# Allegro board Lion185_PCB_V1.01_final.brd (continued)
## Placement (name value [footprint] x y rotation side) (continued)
R170  2k  [RC0402N]  64.46 122.28 270 top
R171  2k  [RC0402N]  64.47 124.04 90 top
R176  0  [RC0402N]  13.18 36.71 270 top
R178  1M  [RC0402N]  7.56 38.57 0 bottom
R182  1M  [RC0402N]  14.13 34.48 270 top
R184  4.7K  [RC0402N]  52.99 116.09 180 bottom
R185  4.7K  [RC0402N]  65.76 114.96 0 top
R186  4.7K  [RC0402N]  57.01 111.9 270 bottom
R187  4.7K  [RC0402N]  63.72 119.33 270 top
R188  4.7K  [RC0402N]  63.72 117.56 90 top
R189  4.7K  [RC0402N]  57.78 111.9 90 bottom
R190  0  [RC0402N]  94.16 44.17 270 bottom
R191  0  [RC0402N]  94.92 44.17 270 bottom
R192  620  [RC0402N]  144.66 99.61 180 bottom
R193  620  [RC0402N]  144.66 100.42 180 bottom
R194  620  [RC0402N]  144.66 101.2 180 bottom
R195  620  [RC0402N]  144.66 101.98 180 bottom
R196  620  [RC0402N]  144.66 102.76 180 bottom
R197  620  [RC0402N]  144.66 103.54 180 bottom
R198  620  [RC0402N]  144.66 104.31 180 bottom
R199  100k  [RC0402N]  145.92 95.24 90 bottom
R200  620  [RC0402N]  144.66 105.08 180 bottom
R201  1k  [RC0402N]  142.33 110.92 180 bottom
R202  2.2K  [RC0402N]  151.44 101.07 90 bottom
R203  2.2K  [RC0402N]  151.44 98.69 270 bottom
R204  2.2K  [RC0402N]  146.83 102.02 90 bottom
R205  2.2K  [RC0402N]  146.83 99.64 270 bottom
R206  0  [RC0603N]  68.98 46.84 0 bottom
R207  0  [RC0603N]  68.24 48.83 270 bottom
R208  0  [RC0402N]  70.72 43.51 90 bottom
R209  2.49K+/-1  [RC0603N]  60.79 45.45 270 bottom
R210  10k  [RC0402N]  53.67 40.9 0 bottom
R211  0  [RC0603N]  48.12 42.93 90 bottom
R212  1k  [RC0402N]  70.72 45.29 90 bottom
R213  10k  [RC0402N]  51.47 40.86 0 bottom
R214  0  [RC0603N]  46.76 42.93 270 bottom
R215  0  [RC0603N]  47.39 40.94 180 bottom
R216  0  [RC0402N]  51.58 38.89 180 bottom
R217  1k  [RC0402N]  51.6 36.5 180 bottom
R218  0  [RC0402N]  51.59 35.69 180 bottom
R219  15K  [RC0402N]  51.6 37.26 180 bottom
R220  0  [RC0603N]  53.59 34.7 180 bottom
R223  10k  [RC0402N]  59.69 35.99 270 bottom
R226  1K  [RC0402N]  54.5 45.59 270 bottom
R235  0  [RC0402N]  137.74 27.16 270 bottom
R236  0  [RC0402N]  118.49 9.2 0 bottom
R237  10k  [RC0402N]  120.99 9.21 180 bottom
R238  75  [RC0402N]  135.41 17.81 180 bottom
R239  10k  [RC0402N]  120.99 9.99 180 bottom
R240  0  [RC0402N]  109.94 17 180 bottom
R241  75  [RC0402N]  135.24 18.59 180 bottom
R242  1K  [RC0603N]  132.44 26.99 90 bottom
R243  0  [RC0402N]  111.32 12.33 0 bottom
R244  4.7K  [RC0402N]  135.86 21.62 270 top
R245  1K  [RC0603N]  131.16 26.99 90 bottom
R246  4.7K  [RC0402N]  135.03 21.62 270 top
R247  0  [RC0402N]  26.28 45.51 270 bottom
R248  0  [RC0402N]  86 36.04 180 bottom
R249  4.7K  [RC0402N]  130.13 32.77 90 bottom
R251  39.2K  [RC0402N]  126.07 23.8 270 bottom
R252  20K  [RC0402N]  127.64 23.8 90 bottom
R256  20K  [RC0402N]  126.85 23.8 270 bottom
R258  0  [RC0603N]  123.06 20.05 180 bottom
R260  0  [RC0603N]  123.06 21.27 180 bottom
R262  33  [RC0402N]  124.37 19.06 180 bottom
R267  10k  [RC0402N]  133.3 23.78 0 top
R268  10k  [RC0402N]  133.3 23 0 top
R269  10k  [RC0402N]  115.38 16.82 0 bottom
R270  10k  [RC0402N]  119.59 19.02 270 bottom
R271  100k  [RC0402N]  119.59 20.81 90 bottom
R272  0  [RC0402N]  115.48 19 270 bottom
R275  1K  [RC0402N]  120.04 24.12 0 bottom
R278  0  [RC0402N]  48.98 33.01 90 bottom
R279  0  [RC0402N]  42.98 42.33 180 bottom
R280  0  [RC0402N]  43.18 46.34 0 bottom
R281  0  [RC0402N]  43.18 47.14 0 bottom
R282  0  [RC0402N]  51.31 54.72 0 bottom
R283  0  [RC0603N]  126.76 10.96 90 bottom
R284  0  [RC0603N]  125.55 10.96 90 bottom
R285  0  [RC0603N]  129.22 11.74 90 bottom
R286  0  [RC0603N]  127.98 11.09 90 bottom
R290  0  [RC0402N]  106.07 40.16 180 bottom
R291  0  [RC0402N]  106.07 40.93 180 bottom
R292  0  [RC0402N]  101.79 44.17 90 bottom
R293  0  [RC0402N]  90.38 104.88 135 bottom
R296  10k  [RC0402N]  96.78 46.16 270 bottom
R297  10k  [RC0402N]  97.85 46.15 270 bottom
R298  10k  [RC0402N]  108.54 22.69 90 bottom
R299  10k  [RC0402N]  93.36 44.17 270 bottom
R300  10k  [RC0402N]  95.72 44.17 270 bottom
R301  0  [RC0402N]  86 35.03 180 bottom
R302  10k  [RC0402N]  98.71 44.15 270 bottom
R304  0  [RC0603N]  109.12 36.53 0 bottom
R307  0  [RC0402N]  87 39.49 90 bottom
R308  0  [RC0402N]  23.84 36.15 180 top
R310  10k  [RC0402N]  86 36.84 0 bottom
R311  5.6k  [RC0402N]  107.38 30.39 270 bottom
R312  100  [RC0402N]  106.12 30.11 0 bottom
R313  10k  [RC0402N]  111.46 30.76 90 bottom
R314  100k  [RC0402N]  110.22 28.73 270 bottom
R315  10k  [RC0402N]  99.84 44.15 270 bottom
R316  10k  [RC0402N]  86 37.62 0 bottom
R317  0  [RC0402N]  108.76 45.64 90 bottom
R318  0  [RC0402N]  109.12 34.28 180 bottom
R319  0  [RC0402N]  107.08 27.22 90 bottom
R320  10k  [RC0402N]  105.51 27.65 270 bottom
R321  0  [RC0402N]  109.05 39.51 180 bottom
R322  0  [RC0402N]  89.83 44.09 90 bottom
R323  0  [RC0402N]  96.68 24.46 90 bottom
R324  0  [RC0402N]  106.09 33.78 180 bottom
R325  0  [RC0402N]  95.91 24.46 270 bottom
R326  20K  [RC0402N]  109.45 28.73 270 bottom
R327  100k  [RC0402N]  113.85 47.08 180 bottom
R328  0  [RC0402N]  106.11 31.66 0 bottom
R329  0  [RC0402N]  102.71 44.17 270 bottom
R330  10k  [RC0402N]  95.1 24.46 90 bottom
R331  0  [RC0402N]  90.89 44.17 90 bottom
R332  0  [RC0402N]  110.01 25.75 135 bottom
R333  100k  [RC0402N]  106.07 35.5 0 bottom
R334  0  [RC0402N]  76.92 42.02 0 bottom
R335  4.7K  [RC0402N]  106.12 30.87 180 bottom
R336  0  [RC0402N]  11.66 27.23 90 bottom
R337  0  [RC0402N]  86.57 27.41 0 bottom
R338  10k  [RC0402N]  86.18 29.13 0 bottom
R339  0  [RC0402N]  76.45 41.54 270 bottom
R340  10k  [RC0402N]  86.47 32.3 0 bottom
R341  0  [RC0402N]  9.56 23.34 180 top
R342  0  [RC0402N]  8.72 31.63 270 top
R343  0  [RC0402N]  104.49 44.11 270 bottom
R344  10M  [RC0402N]  105.26 43.16 90 bottom
R345  4.7K  [RC0402N]  86.99 45.19 0 bottom
R346  4.7K  [RC0402N]  75.38 45.44 270 bottom
R347  100k  [RC0402N]  73.73 40.63 0 bottom
R348  2K  [RC1206N]  102.89 11.57 90 top
R349  0  [RC0402N]  11.2 30.98 0 top
R350  0  [RC0402N]  12.43 27.23 90 bottom
R351  1M  [RC0402N]  15.06 26.9 0 bottom
R352  1k  [RC0402N]  17.98 39.2 0 top
R353  0  [RC0402N]  20.31 39.92 90 top
R354  27K  [RC0402N]  17.79 26.91 0 bottom
R355  0  [RC0402N]  8.85 26.6 90 bottom
R356  10k  [RC0402N]  15.71 36.25 0 top
R357  0  [RC0603N]  115.93 102.02 270 top
R358  0  [RC0402N]  119.04 104.57 270 top
R359  0  [RC0402N]  11.21 31.83 180 top
R360  0  [RC0603N]  133.93 77.28 0 bottom
R361  0  [RC0603N]  133.93 76.03 0 bottom
R362  0  [RC0603N]  133.86 73.41 0 bottom
R363  1.8k  [RC0603N]  130.56 79.88 0 top
R364  0  [RC0603N]  133.86 74.66 0 bottom
R365  1k  [RC0603N]  130.56 78.67 180 top
R366  1k  [RC0402N]  131.06 72.65 180 top
R367  0  [RC0603N]  133.75 78.59 0 bottom
R368  0  [RC0603N]  133.75 79.84 0 bottom
R369  1.8k  [RC0603N]  144.51 56.37 180 bottom
R370  1k  [RC0603N]  144.51 57.65 0 bottom
R371  1k  [RC0402N]  144.86 50.36 0 bottom
R372  1.8k  [RC0603N]  52.34 16.84 180 bottom
R373  1.8k  [RC0603N]  44.21 23.94 270 top
R374  1k  [RC0603N]  52.37 15.61 0 bottom
R375  1k  [RC0402N]  49.85 17.08 0 bottom
R376  100k  [RC0402N]  28.61 47.68 0 bottom
R377  10k  [RC0402N]  132.95 57.9 270 bottom
R378  10k  [RC0402N]  27.7 45.03 0 bottom
R379  1k  [RC0603N]  45.44 23.94 90 top
R380  1k  [RC0402N]  42.79 25.8 0 top
R381  0  [RC0603N]  135.01 48.11 90 top
R382  0  [RC0603N]  30.45 25.2 270 top
R383  0  [RC0402N]  42.27 105.29 90 top
R384  10k  [RC0402N]  55.12 64.62 180 bottom
R385  0  [RC0402N]  20.88 62.34 270 top
R386  10k  [RC0402N]  8.19 103.47 90 bottom
R387  100k  [RC0402N]  17.99 99.9 270 bottom
R388  0  [RC0402N]  17.16 104.74 180 bottom
R389  0  [RC0402N]  13.58 42.77 180 top
R390  100k  [RC0402N]  24.51 91.29 180 bottom
R391  0  [RC0603N]  3.55 13.12 180 bottom
R392  0  [RC0603N]  6.33 13.12 0 bottom
R408  75  [RC0402N]  76.92 24.46 0 bottom
R409  75  [RC0402N]  74.82 24.46 180 bottom
R421  20K  [RC0603N]  29.49 89.77 0 bottom
R422  20K  [RC0603N]  29.41 85.17 0 bottom
R423  30k  [RC0603N]  29.49 91 180 bottom
R424  13k  [RC0603N]  29.4 83.94 0 bottom
R425  270k  [RC0402N]  27.25 89.85 180 bottom
R426  270k  [RC0402N]  28.93 82.92 0 bottom
R427  10k  [RC0402N]  29.01 86.22 180 bottom
R428  10k  [RC0402N]  29.01 87.03 180 bottom
R429  2.2  [RC0603N]  21.88 95.67 270 bottom
R430  2.2  [RC0603N]  26.05 83.78 0 top
R431  0  [RC0603N]  22.61 81.53 270 bottom
R432  0  [RC0603N]  21.62 92.09 270 bottom
R433  0  [RC0402N]  55.12 70.73 180 bottom
R434  0  [RC0402N]  56.39 71.2 90 bottom
R435  0  [RC0402N]  55.59 71.2 90 bottom
R436  200K  [RC0402N]  55.12 62.94 0 bottom
R437  10k  [RC0402N]  11.39 14.11 0 top
R438  110K  [RC0402N]  55.12 63.7 180 bottom
R439  0  [RC0402N]  60.47 64.88 90 bottom
R440  0  [RC0402N]  55.12 65.4 180 bottom
R441  0  [RC0603N]  39.7 79.61 180 bottom
R442  0  [RC0603N]  54.09 67.57 270 bottom
R443  0  [RC0603N]  41.17 73.9 180 bottom
R444  0  [RC0402N]  49.79 60.39 270 bottom
R445  10k  [RC0402N]  48.78 62.47 270 bottom
R446  75K  [RC0402N]  48.01 64.24 270 bottom
R447  30k  [RC0402N]  47.23 64.24 270 bottom
R448  100k  [RC0402N]  58.25 65.36 180 bottom
R449  10k  [RC0402N]  61.25 64.88 90 bottom
R450  0  [RC0402N]  62.04 64.89 90 bottom
R451  1M  [RC0402N]  58.25 64.57 0 bottom
R452  0  [RC0603N]  83.55 105.97 0 top
R453  0  [RC0402N]  88.29 122.92 90 bottom
R454  100k  [RC0402N]  88.76 121.65 180 bottom
R455  100  [RC0402N]  16.65 38.38 90 top
R456  0  [RC0402N]  21.04 85.31 0 bottom
R457  0  [RC0402N]  131.29 67.9 90 bottom
R458  0  [RC0402N]  122.12 67.68 90 bottom
R459  2.2  [RC0603N]  130.32 66.34 180 bottom
R460  220K  [RC0402N]  131.45 70.63 90 bottom
R461  300  [RC0603N]  132.58 71.13 90 bottom
R462  100k  [RC0402N]  137.64 70.65 90 bottom
R463  0  [RC0603N]  131.8 64.03 180 bottom
R464  10k  [RC0603N]  135.61 62.46 0 bottom
R465  100k  [RC0402N]  21.06 83.59 0 bottom
R466  0  [RC0402N]  136.87 70.65 270 bottom
R467  0  [RC0603N]  137.17 64.75 90 bottom
R468  10k  [RC0603N]  135.83 71.15 90 bottom
R469  100k  [RC0402N]  109.81 71.67 0 bottom
R470  30k  [RC0603N]  134.62 71.15 270 bottom
R471  100K  [RC0402N]  111.62 71.67 0 bottom
R472  0  [RC0402N]  75.02 113.43 0 bottom
R473  7.5k  [RC0402N]  131.51 57.46 180 bottom
R474  100K  [RC0402N]  131.64 53.87 180 bottom
R475  24k  [RC0402N]  131.51 56.69 180 bottom
R476  0  [RC0402N]  131.64 53.04 0 bottom
R477  100K  [RC0402N]  131.5 55.89 180 bottom
R478  1  [RC0805N]  27.9 32.58 180 top
R479  0  [RC0402N]  31.96 61.73 270 bottom
R480  15k  [RC0603N]  31.79 58.64 90 bottom
R481  1  [RC0805N]  27.9 36.05 180 top
R482  12k  [RC0402N]  31.32 60.39 180 bottom
R483  100K  [RC0402N]  31.18 61.73 270 bottom
R484  0  [RC0402N]  92.88 115.92 180 bottom
R485  1  [RC0805N]  27.9 34.31 180 top
R486  0  [RC0402N]  29.01 88.64 0 bottom
R487  21.5k  [RC0603N]  37.51 50.45 0 bottom
R488  100K  [RC0402N]  33.47 48.79 0 bottom
R489  24k  [RC0402N]  37.24 49.43 0 bottom
R490  0  [RC0402N]  35.28 48.79 0 bottom
R491  100K  [RC0402N]  21.06 84.4 180 bottom
R492  10k  [RC0402N]  94.94 106.65 270 top
R493  0  [RC0402N]  122.89 67.68 90 bottom
R494  12k  [RC0402N]  93.36 114.65 90 bottom
R495  100K  [RC0402N]  92.88 116.71 0 bottom
R496  24k  [RC0402N]  92.58 114.65 270 bottom
R497  0  [RC0402N]  115.48 121.41 90 top
R498  100K  [RC0402N]  31.65 48.79 180 bottom
R499  1  [RC0805N]  27.9 37.84 180 top
R500  100k  [RC0402N]  134.57 55.08 180 bottom
R501  0  [RC0402N]  142.34 111.69 0 bottom
R502  0  [RC0402N]  142.34 112.47 0 bottom
R503  100K  [RC0402N]  132.97 53.52 270 bottom
R504  100k  [RC0402N]  89.87 127.16 180 bottom
R505  270k  [RC0402N]  117.8 115.24 270 top
R506  75K  [RC0402N]  119.08 114.84 0 top
R507  10.7K  [RC0603N]  118.76 116.73 180 top
R508  100  [RC0402N]  118.26 118.5 0 top
R509  100  [RC0402N]  118.26 119.31 0 top
R510  0  [RC0402N]  88.76 122.44 0 bottom
R511  34K  [RC0402N]  129.13 101.53 45 bottom
R512  100K_NTC  [RC0402N]  129.14 102.69 225 bottom
R513  0  [RC0402N]  117.03 121.41 270 top
R514  10  [RC0402N]  118.14 111.27 270 top
R515  30k  [RC0402N]  118.9 115.08 225 bottom
R516  73.2  [RC0402N]  112.28 123.43 270 top
R517  73.2  [RC0402N]  113.1 123.43 270 top
R518  73.2  [RC0402N]  113.92 123.43 270 top
R519  28.7K  [RC0402N]  130.39 102.79 225 bottom
R520  0  [RC0603N]  120.38 100.72 270 top
R521  2.2  [RC0603N]  115.93 111 90 top
R522  20  [RC0402N]  113.92 121.41 270 top
R523  0  [RC0402N]  113.1 121.41 270 top
R524  2.2  [RC0603N]  113.5 111 90 top
R525  16.9  [RC0402N]  112.28 121.41 270 top
R526  0  [RC0603N]  120.42 106.07 90 top
R527  10k  [RC0402N]  111.21 111.44 90 top
R528  33  [RC0402N]  111.42 121.41 270 top
R529  0  [RC0402N]  108.55 119.63 0 top
R530  100  [RC0402N]  108.55 118.87 180 top
R531  100k  [RC0402N]  109.65 121.36 270 top
R532  33K  [RC0402N]  96.28 128.17 180 bottom
R533  11K  [RC0603N]  108.08 117.06 270 top
R534  210K  [RC0402N]  108.33 115.02 0 top
R535  100K_NTC  [RC0402N]  95.43 127.39 0 bottom
R536  30k  [RC0402N]  109.04 116.64 90 bottom
R537  100K  [RC0402N]  114.7 121.41 90 top
R538  75K  [RC0402N]  106.15 114.95 180 top
R539  28.7K  [RC0402N]  94.5 128.17 0 bottom
R540  2.2  [RC0603N]  99.29 113.28 270 top
R541  2.2  [RC0603N]  95.97 124.16 0 top
R542  665k  [RC0402N]  119.24 121.87 270 top
R543  169K  [RC0402N]  110.49 123.31 270 top
R544  665k  [RC0402N]  107.61 121.49 270 top
R545  15.8k  [RC0402N]  119.79 113.87 180 top
R546  15.8k  [RC0402N]  106.18 113.87 0 top
R547  0  [RC0402N]  106.18 112.7 0 top
R548  0  [RC0402N]  106.18 111.61 0 top
R549  39k  [RC0603N]  119.1 120.33 0 top
R550  150k  [RC0402N]  110.49 121.41 90 top
R551  39k  [RC0603N]  108.6 121.76 90 top
R552  100K_NTC  [RC0402N]  118 113.87 180 top
R553  100K_NTC  [RC0402N]  108.31 113.87 0 top
R554  150k  [RC0402N]  108.31 112.7 180 top
R555  150k  [RC0402N]  108.31 111.61 180 top
R556  100K  [RC0402N]  15.05 64.61 0 top
R557  10k  [RC0402N]  26.87 64.36 180 top
R558  100k  [RC0402N]  25.55 61.4 270 top
R559  10k  [RC0402N]  40.98 104.82 180 top
R560  0  [RC0402N]  20.88 63.29 270 top
R561  0  [RC0402N]  106.39 74.3 270 bottom
R562  100k  [RC0402N]  143.37 63.87 180 top
R564  0  [RC0603N]  50.48 26.02 0 top
R565  470  [RC0402N]  23.43 44.18 0 bottom
R566  0  [RC0603N]  50.47 24.8 0 top
R567  470  [RC0402N]  149.06 61.28 0 top
R568  0  [RC0603N]  136.26 48.1 90 top
R569  470  [RC0402N]  32.59 100.1 0 top
R570  470  [RC0402N]  13.26 65.05 90 top
R571  470  [RC0402N]  123.33 76.14 270 top
R572  470  [RC0402N]  29.21 55.44 0 bottom
R573  470  [RC0402N]  90.93 116.1 270 bottom
R574  1M  [RC0402N]  143.37 63.03 0 top
R575  0  [RC0603N]  29.25 25.21 270 top
R576  470  [RC0402N]  61.8 63.08 90 bottom
R577  75  [RC0402N]  62.09 22.77 180 bottom
R578  0  [RC0402N]  118.2 81.59 45 bottom
R579  1k  [RC0402N]  119.59 78.81 90 bottom
R580  73.2  [RC0402N]  117.69 78.8 90 bottom
R581  0  [RC0402N]  65.7 44.84 180 bottom
R582  51  [RC0402N]  110.79 99.46 90 top
R583  51  [RC0402N]  111.61 99.46 90 top
R584  51  [RC0402N]  110.49 98.13 180 top
R585  0  [RC0402N]  78.1 82.03 180 bottom
R586  20  [RC0402N]  105 91.12 0 top
R587  16.9  [RC0402N]  105 89.6 0 top
R588  0  [RC0402N]  105 90.36 0 top
R589  0  [RC0402N]  39.53 43.46 135 bottom
R590  100k  [RC0402N]  33.3 45.96 90 bottom
R591  0  [RC0402N]  86.24 34.24 180 bottom
R592  0  [RC0402N]  89.87 24.8 0 bottom
R593  0  [RC0402N]  71.49 43.51 90 bottom
R594  0  [RC0603N]  41.28 60.31 270 bottom
R595  100k  [RC0402N]  42.23 62.19 180 bottom
R596  75  [RC0402N]  64.12 22.77 0 bottom
R597  10k  [RC0402N]  9.39 120.81 0 bottom
R598  0  [RC0402N]  42.71 63.5 270 bottom
R599  0  [RC0402N]  43.18 63.03 0 bottom
R600  10k  [RC0402N]  123.75 24.74 90 bottom
R601  1K  [RC0402N]  124.51 24.74 270 bottom
R602  10k  [RC0402N]  103.82 95.63 270 top
R603  0  [RC0603N]  82.15 23.19 90 bottom
R604  0  [RC0603N]  80.9 23.19 90 bottom
R605  0  [RC0402N]  21.87 39.92 90 top
R606  0  [RC0402N]  86.25 33.45 180 bottom
R607  0  [RC0402N]  61.53 126.51 180 top
R608  0  [RC0402N]  59.75 126.51 0 top
R609  0  [RC0402N]  57.82 126.52 180 top
R610  0  [RC0402N]  56.05 126.52 0 top
R611  0  [RC0402N]  55.25 124.06 180 top
R612  0  [RC0402N]  53.16 124.06 0 top
R613  0  [RC0402N]  52.34 125.59 180 top
R614  0  [RC0402N]  50.27 125.59 0 top
R615  0  [RC0402N]  49.17 122.45 180 top
R616  100k  [RC0402N]  15.71 37.11 180 top
R617  0  [RC0603N]  65.28 21.05 90 top
R618  0  [RC0603N]  64.05 21.05 90 top
R619  430k  [RC0603N]  15.06 26.9 0 bottom
R620  0  [RC0603N]  70.48 24 180 bottom
R621  0  [RC0805N]  5.12 20.49 0 top
R622  0  [RC0603N]  70.47 22.79 180 bottom
R623  0  [RC0603N]  66.18 19.83 180 bottom
R624  0  [RC0603N]  66.18 21.08 180 bottom
R625  0  [RC0402N]  7.95 110.15 0 top
R626  22k  [RC0402N]  23.84 34.51 180 top
R627  0  [RC0402N]  7.95 111.1 0 top
R628  0  [RC0402N]  13.58 43.54 0 top
R629  0  [RC0402N]  14.56 39.01 0 top
R630  10k  [RC0402N]  66.07 98.21 0 top
R631  10k  [RC0402N]  66.07 99 0 top
R632  0  [RC0402N]  61.22 35.99 270 bottom
R633  0  [RC0402N]  60.46 35.99 270 bottom
R634  0  [RC0402N]  52.49 31.4 135 bottom
R635  0  [RC0402N]  46.67 34.58 315 bottom
R636  0  [RC0402N]  49.14 31.19 90 bottom
R637  10k  [RC0402N]  37.42 44.91 270 bottom
R638  10k  [RC0402N]  120.39 86.31 270 bottom
R639  0  [RC0402N]  24.94 30.46 0 top
R641  0  [RC0402N]  15.71 35.44 0 top
R642  0  [RC0402N]  21.13 32.26 90 top
R643  0  [RC0402N]  15.71 34.65 0 top
R644  10k  [RC0402N]  105.61 74.3 270 bottom
R645  0  [RC0402N]  113.85 72.81 270 bottom
R646  1  [RC0805N]  23.2 38.32 270 top
R647  0  [RC0402N]  112.54 31.44 90 bottom
R648  0  [RC0402N]  102.32 22.96 90 bottom
R649  0  [RC0402N]  62.81 89.27 180 bottom
R650  0  [RC0402N]  63.29 89.74 90 bottom
R651  0  [RC0402N]  113.31 31.44 90 bottom
R652  0  [RC0402N]  114.08 31.44 90 bottom
R653  0  [RC0402N]  103.09 22.96 90 bottom
R654  0  [RC0402N]  103.86 22.96 90 bottom
R655  0  [RC0402N]  104.64 22.96 90 bottom
R656  0  [RC0402N]  114.86 31.44 90 bottom
R657  0  [RC0402N]  82.04 37.88 0 bottom
R658  0  [RC0402N]  91.67 44.17 270 bottom
R659  0  [RC0402N]  95.99 45.97 90 bottom
R660  0  [RC0402N]  13.57 44.33 0 top
R661  10k  [RC0402N]  23.75 32.77 180 bottom
R662  100k  [RC0402N]  17.71 89.26 90 bottom
R663  1M  [RC0402N]  16.95 89.26 270 bottom
R664  0  [RC0402N]  14.51 83.01 270 bottom
R665  0  [RC0402N]  21.56 82.32 90 bottom
R666  0  [RC0603N]  102.17 115.09 180 bottom
R667  0  [RC0603N]  101.63 117.78 0 bottom
R668  0  [RC0603N]  137.7 31.2 90 top
R669  0  [RC0603N]  137.7 34.9 270 top
R670  0  [RC0805N]  85.51 40.27 90 bottom
R671  0  [RC0402N]  90.92 105.42 135 bottom
R672  0  [RC0402N]  98.85 46.24 270 bottom
R673  0  [RC0402N]  99.7 46.24 270 bottom
R674  0  [RC0402N]  86.61 26.42 0 bottom
R675  1K  [RC0402N]  24.51 92.11 0 bottom
R676  0  [RC0603N]  84.13 107.19 0 top
R677  0  [RC0603N]  116.9 75.67 90 top
R678  0  [RC0603N]  115.69 75.67 90 top
R679  0  [RC0402N]  7.86 106.39 135 bottom
R680  0  [RC0603N]  137.7 22.93 270 top
R681  0  [RC0402N]  20.33 32.26 90 top
R682  10k  [RC0402N]  64.74 77.5 90 bottom
R683  10k  [RC0402N]  63.66 75.15 90 bottom
R684  10k  [RC0402N]  64.43 75.15 90 bottom
R685  1K  [RC0402N]  129.95 26.31 270 top
R686  10k  [RC0402N]  130.95 43.83 180 bottom
R687  1M  [RC0402N]  131.42 45.63 90 bottom
R688  22.1k  [RC0402N]  129.81 48.7 180 bottom
R689  100k  [RC0402N]  127.73 49.2 270 bottom
R690  680  [RC0402N]  29.85 118.43 180 bottom
R691  10k  [RC0402N]  36.81 117.93 270 top
R692  10k  [RC0402N]  36.28 115.62 90 top
R693  0  [RC0603N]  30.94 126.57 90 top
R694  100k  [RC0402N]  33.18 126.08 90 top
R695  0  [RC0603N]  23.33 112.32 90 top
R696  499K  [RC0402N]  34.51 126.57 180 top
R697  4.7K  [RC0402N]  34.51 125.79 0 top
R698  47K  [RC0402N]  35.5 115.62 90 top
R699  0  [RC0603N]  137.7 16.02 90 top
R700  0  [RC0603N]  111.74 34.77 270 bottom
R701  0  [RC0402N]  99.36 24.36 0 bottom
R702  0  [RC0402N]  99.36 23.6 0 bottom
R703  100k  [RC0402N]  26.06 32.77 0 bottom
R704  0  [RC0402N]  101.14 24.36 180 bottom
R707  1  [RC0805N]  24.99 38.32 270 top
R708  0  [RC0603N]  128.57 42.58 0 bottom
R709  100k  [RC0402N]  113.95 80.28 180 top
R710  10k  [RC0402N]  12.55 33.14 90 top
R711  1k  [RC0402N]  138.17 20.42 0 top
R712  0  [RC0402N]  65.35 81.17 90 top
R713  0  [RC0402N]  18.99 100.85 270 bottom
R714  0  [RC0402N]  30.41 61.73 90 bottom
R715  0  [RC0402N]  29.64 61.73 270 bottom
R716  0  [RC0402N]  3.57 106.74 270 bottom
R717  0  [RC0402N]  92.55 44.17 90 bottom
R718  0  [RC0402N]  46.75 50.91 90 bottom
R719  1k  [RC0402N]  138.17 18.54 0 top
R720  0  [RC2512N]  116.83 19.69 90 top
R721  10k  [RC0402N]  148.58 128.61 180 bottom
R722  147K  [RC0603N]  6.36 109.59 180 bottom
R723  59K  [RC0402N]  6.08 110.59 0 bottom
R724  0  [RC0402N]  4.3 100.65 270 bottom
R725  43K  [RC0603N]  7.57 98.94 270 bottom
R726  39k  [RC0603N]  6.98 100.91 180 bottom
R727  68K  [RC0402N]  4.45 108.53 270 bottom
R728  499K  [RC0402N]  4.45 106.74 90 bottom
R729  10k  [RC0402N]  65.24 93 0 top
R730  10k  [RC0402N]  62.93 96.81 0 bottom
R731  0  [RC0603N]  108.15 95.39 180 bottom
R732  0  [RC0402N]  28.33 62.22 180 bottom
R733  0  [RC0402N]  127.04 70.75 270 bottom
R734  0  [RC0402N]  28.33 62.99 180 bottom
R735  47K  [RC0402N]  148.58 127.81 180 bottom
R736  10k  [RC0402N]  149.86 125.21 90 bottom
R737  680  [RC0402N]  140.24 128.19 270 bottom
R738  0  [RC0603N]  147.93 112.38 0 bottom
R739  499K  [RC0402N]  147.27 116.86 90 bottom
R740  4.7K  [RC0402N]  146.5 116.86 270 bottom
R741  100k  [RC0402N]  145.71 116.86 270 bottom
R742  0  [RC0603N]  143.61 116.67 270 bottom
R743  0  [RC0402N]  4.35 122.49 90 bottom
R744  2.2  [RC0805N]  104.9 12.39 90 top
R745  0  [RC0402N]  47.26 51.39 180 bottom
R746  0  [RC0402N]  45.96 50.91 90 bottom
R747  0  [RC0402N]  45.45 51.39 0 bottom
R748  0  [RC0402N]  21.93 32.31 270 top
R749  0  [RC0402N]  25.41 29.99 90 top
R750  100k  [RC0402N]  9.61 35.19 270 bottom
R751  0  [RC0402N]  12.55 34.91 270 top
R761  0  [RC0805N]  42.25 127.71 180 top
R762  0  [RC0805N]  42.24 125.96 180 top
R800  10k  [RC0402N]  131.2 127.85 90 bottom
R801  1k  [RC0402N]  133.61 127.85 270 bottom
R802  100k  [RC0402N]  132.07 127.85 270 bottom
R803  0  [RC0402N]  122.73 111.49 0 top
R804  0  [RC0402N]  122.72 117.44 0 top
R805  0  [RC0402N]  122.72 116.61 0 top
R883  36K  [RC0603N]  17.79 26.91 180 bottom
R898  0  [RC0402N]  131.38 41.82 90 top
R899  390K  [RC0603N]  131.69 29.5 0 top
R900  100k  [RC0402N]  136.05 41.81 270 top
R901  100k  [RC0402N]  134.29 33.91 270 top
R902  100  [RC1206N]  121.53 20.64 90 top
R903  1M  [RC0402N]  133.99 30.74 180 top
R904  0  [RC0402N]  136.86 41.81 270 top
R958  180K  [RC0402N]  23.84 35.31 180 top
R959  475k  [RC0402N]  12.94 83.01 270 bottom
R960  100k  [RC0402N]  13.71 83.01 90 bottom
R1114  10k  [RC0402N]  11.62 37.65 0 top
SW1  TMG-533-S-T/R(180GF)  [SW_TMG-53N]  16.18 51.7 0 top
SW2  SKRMABE010  [SW_330X390P_4N]  16.17 51.71 270 top
SW4  TMG-533-S-T/R(180GF)  [SW_TMG-53N]  19.42 114.17 270 bottom
TP1  TP  [TEST80]  98.93 83.51 180 bottom
TP2  TP  [DOT]  90.81 93.39 180 bottom
TP3  TP  [DOT]  85.59 83.74 180 bottom
TP4  TP  [DOT]  87.31 88.2 180 bottom
TP5  TP  [TEST120]  68.33 93.03 0 top
TP6  TP  [TEST120]  61.01 93.97 180 bottom
TP7  TP  [TEST80]  71.02 89.05 180 bottom
TP8  TP  [TEST80]  72.58 89.05 180 bottom
TP9  TP  [TEST80]  98.9 85.66 180 bottom
U1  VLV_M_D  [BGA71P53X56-1170N]  85.74 85.55 90 top
U3  EN25S64-104RIP  [VSOP127P790-8N]  113.47 91.3 90 top
U5  TPS22965  [SON50P200X200-8N]  116.73 84.84 180 top
U6  TXB0104RUTR  [UQFN40P200X170-12N]  119.38 76.79 0 top
U7  EMC1402  [TSOP65P490-8N]  58.87 61.04 0 top
U8  TPS22965  [SON50P200X200-8N]  46.37 128.79 90 top
U9  APL3512A/B  [SOT95P280-5N]  11.99 40.27 90 top
U10  PS8625QFN56G  [QFN40P700X700-56AN]  57.83 117.1 180 bottom
U12  AT24C02A  [SOIC127P600-8N]  67.56 127.64 270 top
U13  AT24C02A  [SOIC127P600-8N]  67.64 119.23 270 top
U14  TPD8S009  [S0N50P250X650-15N]  140.19 102.11 0 top
U15  APL3517  [SOT95P280-3N]  141.07 96.13 270 bottom
U16  TPS22965  [SON50P200X200-8N]  68.88 45.15 180 bottom
U17  RTL8105E/8111E  [QFN40P600X600-48N]  58.06 40.58 180 bottom
U19  APL3512A/B  [SOT95P280-5N]  120.22 12.04 180 bottom
U20  TPS22965  [SON50P200X200-8N]  109.97 18.31 0 bottom
U21  APL3512A/B  [SOT95P280-5N]  135.22 26.68 0 bottom
U22  APL3512A/B  [SOT95P280-5N]  111.37 14.38 180 bottom
U23  ALC282  [QFN40P600X600-48AN]  129.49 18.51 0 bottom
U24  5_SN74LVC1G08DCKR  [SOT65P190-5N]  117.52 15.87 270 bottom
U25  APW7228  [QFN50P400X400-24AN]  19.68 36.17 90 top
U26  TXB0104RUTR  [UQFN40P200X170-12N]  106.65 22.94 90 bottom
U27  TXB0104RUTR  [UQFN40P200X170-12N]  109.88 31.36 90 bottom
U28  IT8528E/VG  [LQFP40P1600X1600-128N]  96.08 34.01 180 bottom
U29  SN74LVC1G06DCK  [SOT65P210-5N]  73.94 42.8 90 bottom
U30  EN25F16-100HIP  [SOIC127P800-8N]  80.65 45.28 0 bottom
U31  TPS2065  [SOT95P280-5N]  131.54 75.15 270 top
U32  TPD2EUSB30DRTR  [SOP35P100-3N]  135.89 74.04 90 bottom
U33  TPD2EUSB30DRTR  [SOP35P100-3N]  135.78 79.19 90 bottom
U34  SN74AHC1G08  [SOT65P210-5N]  8.19 106.14 90 bottom
U36  SN74AHC1G32  [SOT65P210-5N]  10.89 106.14 270 bottom
U37  SN74AHC1G08  [SOT65P210-5N]  17.64 106.5 180 bottom
U38  SN74AHC1G08  [SOT65P210-5N]  13.46 106.13 270 bottom
U39  SN74AHC1G32  [SOT65P210-5N]  17.34 102.56 270 bottom
U40  SN74AHC1G08  [SOT65P210-5N]  14.76 102.57 270 bottom
U41  TPS2065  [SOT95P280-5N]  51.58 19.12 180 bottom
U42  TPS51125RGE  [PVQFN50P480X480-24N]  24.78 86.7 180 bottom
U43  TPS51216  [QFN40P300X300-20N]  51.64 63.53 90 bottom
U44  TPS22965  [SON50P200X200-8N]  87.8 119.5 270 bottom
U45  TPS22965  [SON50P200X200-8N]  77.35 113.18 0 bottom
U46  TPS22965  [SON50P200X200-8N]  120.23 68.4 180 bottom
U47  TPS51117RGY  [PQFP50P365X365-14N]  134.12 67.09 0 bottom
U48  TPS22965  [SON50P200X200-8N]  114.36 75.18 90 bottom
U49  APL5932C/D  [TDFN50P300X300-10N]  128.8 56.16 270 bottom
U50  APL5932C/D  [TDFN50P300X300-10N]  34.13 60.86 90 bottom
U51  TPS22965  [SON50P200X200-8N]  56.6 84.58 0 top
U52  APL5932C/D  [TDFN50P300X300-10N]  34.21 50.95 180 bottom
U53  APL5932C/D  [TDFN50P300X300-10N]  95.67 114.17 0 bottom
U54  TPS22965  [SON50P200X200-8N]  92.57 109.19 180 top
U55  TPS2065  [SOT95P280-5N]  144.31 52.87 270 bottom
U56  TPS59641TSL  [QFN40P600X600-48AN]  113.41 116.7 180 top
U57  TPS51604  [SON50P200X200-8N]  101.57 114.57 90 top
U58  SN74LVC1G08DCKR  [SOT65P190-5N]  39.22 43.49 270 bottom
U59  TPS2065  [SOT95P280-5N]  41.9 23.26 90 top
U60  TPS22965  [SON50P200X200-8N]  42.7 60.31 270 bottom
U61  HS00-04078  [SMD-TRANSF-127P-16N]  75.84 30.24 270 bottom
U62  HS00-04078  [SMD-TRANSF-127P-16N]  62.44 28.6 270 bottom
U63  SN74LVC1G08DCKR  [SOT65P190-5N]  24.09 32.14 0 top
U65  TXS0102DQER  [SON35P100-8N]  67.89 98.65 180 top
U68  TPS22965  [SON50P200X200-8N]  17.55 65.54 0 top
U69  TPS22965  [SON50P200X200-8N]  37.47 101.67 90 top
U70  APL5320-18BI  [SOT95P280-5N]  79.78 39.93 180 bottom
U71  SN74AHC1G32  [SOT65P210-5N]  17.03 83.19 0 bottom
U73  APL3512A/B  [SOT95P280-5N]  116.98 102.02 90 top
U74  TXS0102DQER  [SON35P100-8N]  63.54 77.49 270 bottom
U75  KH25U6439FZNI-10G  [SON127P500X600-8AN]  113.47 91.3 90 top
U76  SY8200ABC  [SOT95P280-6FN]  129.33 46.36 270 bottom
U77  GL850G-SSOP28  [SSOP65P780-28N]  31.11 120.8 90 top
U79  TLV3492  [SOT65P280-8N]  4.62 103.65 270 bottom
U83  GL850G-SSOP28  [SSOP65P780-28N]  144.15 122.34 270 bottom
U84  APL3512A/B  [SOT95P280-5N]  7.67 122.97 180 bottom
U95  GL834L  [QFN50P400X400-24BN]  132.58 123.72 180 bottom
X1  X3S025000FK1H  [OSC170P320X250-4N]  90.14 103.72 180 top
X2  Q13MC1461000200SM26BSPRC  [OSC127P200X600-2L]  111.94 102.5 90 top
X3  32.768KHz  [OSC120P150X670-4L]  110.26 102.5 90 top
X4  X3S025000FK1H  [OSC170P320X250-4N]  58.46 48.65 0 bottom
X5  Q13MC1461000200SM26BSPRC  [OSC127P200X600-2L]  113.11 43.18 270 bottom
X6  32.768KHz  [OSC120P150X670-4L]  112.15 43.18 270 bottom
X7  12MHz  [OSC170P320X250-4N]  30.28 111.87 0 top
X8  12MHz  [OSC170P320X250-4N]  143.6 131.35 0 bottom

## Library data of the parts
C1 C3-C13 C101-C107 C138 C140-C144 C153-C155 C157 C314 C315 C520 C522-C526 = C: signal model: C_CC0402N_100NF_100NF
C14 C16-C21 C28-C40 C43-C45 C49-C75 C79-C81 C83-C99 C108-C128 C130-C137 C150 C152 C160-C162 C164 C166 C169 C171 C172 C183-C187 C190-C196 C198 C200-C207 C211 C222 C223 C225 C227-C229 C231-C240 C242-C257 C259-C271 C275 C281-C294 C299-C303 C305 C309 C312 C313 C317 C318 C320 C321 C323-C326 C328-C332 C334 C336 C338 C360-C362 C365-C371 C373 C375 C377-C382 C384 C385 C387 C389-C404 C406-C411 C413-C455 C457-C460 C462-C469 C473-C480 C484-C490 C492-C514 C517-C519 C521 C527 C529 C535-C540 C542-C584 C596 C597 C601 C603 C606 C608-C618 C620-C622 C700-C702 C704-C710 C726 C764-C767 C942 C992 = C
C22 C25 = C: alternate symbols: (T:CC0603N;B:CC0603M); signal model: C_CC0402N_0.01UF_0.01uF
C23 C24 C41 C42 C129 C151 C188 C210 C224 C226 C230 C241 C304 C337 C363 C364 C372 C374 C376 C383 C386 C388 C405 C412 C456 C461 C491 C515 C516 C585-C587 C599 C600 C602 C605 C607 C619 C727 C845 = C: alternate symbols: (T:CC0603N;B:CC0603M)
C26 C27 C156 C159 C163 C165 C273 C274 = C: signal model: C_CC0402N_0.01UF_0.01uF
C46-C48 C76-C78 C470-C472 C481-C483 C703 = C: alternate symbols: (T:CC0805N;B:CC0805M)
C100 = C: alternate symbols: (T:CC0805N;B:CC0805M); signal model: C_CC0402N_100NF_100NF
C175-C182 C208 C209 = C: signal model: C_CC0402N_0.1U_0.1u
C197 C199 C272 C310 C311 C316 C319 C322 C327 C333 C335 = C: alternate symbols: (T:CC1206N;B:CC1206M)
C296 C297 = C: alternate symbols: (T:CC1206N;B:CC1206M); signal model: C_CC0402N_0.01UF_0.01uF
C298 = C: alternate symbols: (T:CC1210N;B:CC1210M); signal model: C_CC0402N_0.01UF_0.01uF
C598 C604 = C: alternate symbols: (T:CC1210N;B:CC1210M)
CN2 CN19 CN21 = CN2+2-S
CN3 = CN-DDR3-204
CN4 CN13 = CN4+2-S
CN5 CN11 CN17 CN22 CN34 = CN6+2-S
CN6 = CN2-S
CN8 = CN19+4-S
CN9 = CN8+2-d
CN12 = PCI-e_MINI_CARD_52+3
CN14 CN16 CN18 = CN20+2-S
CN15 CN27 CN28 = CN4+4-S
CN20 = CN-SPEAKER-4+2
CN24 CN26 = CN14+2-S
CN30 = CN22+4_3IN1-CARD
CP1 CP4 CP7 CP19 CP25 CP26 CP50 = C_P
CP5 CP6 CP9 CP11-CP14 CP18 CP20 = C_P: alternate symbols: (T:CCP7343N;B:CCP7343M)
D1 D2 D5 D12-D14 D26-D28 D31 D38 D41 D44-D49 = D
D3 D7 D9-D11 D15 D33 D34 = D: alternate symbols: (T:sod2514n;B:SOD2514M)
D6 = D_2PN: alternate symbols: (T:SOT95P280-3N;B:SOT95P280-3M)
D24 D25 = D_2PN
F1-F6 = FUSE
FB1-FB3 FB13 FB16 FB32 = FB: alternate symbols: (T:FB0603N;B:FB0603M)
FB4-FB11 FB14 FB15 FB17 FB18 FB20 FB23-FB25 = FB
FB12 FB34-FB36 = FB: alternate symbols: (T:FB1206N;B:FB1206M)
FIL1-FIL7 FIL12-FIL14 = FIL4_DXW21BN7511TB
J2 = CN-USB-9+2
J3 = SPEAKER_CON_1
J4 J7 = CN-earphone-6_14
J5 = CN10+2-S
J13 = CN-ADPIN_JACK-5-1
L3 L4 L6-L9 L14-L17 L31 = L
MARK1-MARK8 = MARK
MH1-MH10 = H
Q1-Q3 Q7-Q10 Q14 Q16 Q36 Q43 Q45 Q59 Q61 Q62 Q64 Q66 Q68 Q71 Q73-Q77 Q79-Q82 Q84 Q100 Q102 Q103 = NMOS-GSD
Q4 = NPN-BEC: alternate symbols: (T:SOT95P230-3N;B:SOT95P230-3M)
Q5 = NPN-BEC+2R: alternate symbols: (T:SOT65P210-3N;B:SOT65P210-3M)
Q13 Q17 Q67 Q83 Q90 = NMOS-GSD_0
Q25 Q44 Q70 = NMOS-GSD+D2
Q34 Q35 Q37 Q40 = SI4814: alternate symbols: (T:SOIC127P600-8N;B:SOIC127P600-8M)
Q38 Q39 Q46-Q58 Q63 Q69 Q78 Q85 Q86 Q88 Q89 Q97 = NMOS-GSD: alternate symbols: (T:SOT95P240-3N;B:SOT95P240-3M)
Q41 Q87 = 7_SM7302ESKP
Q42 Q98 = PMOS-GSD+D
Q65 = PWR_P_MOSFET: alternate symbols: (T:SOIC127P600-8N;B:SOIC127P600-8M)
Q72 = 3_WNM2020
Q95 = 3_APM1110NU
R1-R19 R22-R26 R31-R46 R51-R55 R57-R65 R67-R69 R76 R78-R100 R103 R105-R112 R114-R137 R149 R155 R159 R161 R163 R164 R169-R171 R176 R178 R182 R184-R189 R192-R200 R203 R205 R209 R210 R212 R213 R216-R218 R223 R237 R238 R241 R244 R246 R247 R249 R251 R252 R267 R268 R278-R286 R290 R296 R297 R300-R302 R307 R308 R310-R344 R347 R349 R350 R352-R356 R358 R359 R363 R366 R369 R371-R373 R375-R378 R380 R383-R385 R387-R389 R391 R392 R408 R409 R421 R422 R424-R428 R433-R440 R444-R451 R453-R458 R460 R462 R464-R466 R468-R470 R472 R476 R479 R482 R484 R486 R490 R492-R494 R497 R500-R502 R504-R511 R513 R515-R519 R521 R524 R527-R534 R536 R538-R551 R554 R555 R557-R562 R573 R574 R577-R586 R589-R592 R595-R600 R602 R605 R606 R619 R625-R636 R638 R639 R641-R645 R647-R660 R662-R669 R671-R674 R679-R684 R686-R699 R701 R702 R704 R709 R711-R717 R719-R727 R729 R730 R732-R743 R745 R747-R749 R800-R805 R883 R898 R900-R904 R959 R960 R1114 = R
R20 R56 R66 R71 R72 R77 R211 R214 R215 R219 R220 R226 R258 R260 R271 R304 R345 R346 R351 R357 R365 R370 R374 R379 R386 R390 R423 R429 R430 R441-R443 R452 R459 R461 R463 R467 R478 R481 R485 R499 R520 R526 R565 R567 R569-R572 R576 R594 R601 R616 R646 R675-R678 R685 R700 R703 R707 R708 R731 R744 R750 R899 R958 = R: alternate symbols: (T:RC0603N;B:RC0603M)
R47-R50 R262 = R: signal model: R_RC0402N_33_33
R70 R73-R75 = R: signal model: R_RC0402N_22_22
R101 R102 R160 R162 R168 R291-R293 R298 R299 R360-R362 R364 R367 R368 R381 R382 R564 R566 R568 R575 R603 R604 R607-R615 R617 R618 R620 R622-R624 R718 R746 = R: signal model: R_RC0402N_0_0
R152 R153 R165 R166 R190 R191 R235 R236 R239 R240 R242 R243 R245 R248 R256 R269 R270 R272 R471 R473-R475 R477 R480 R483 R487-R489 R491 R495 R496 R498 R503 R512 R514 R523 R535 R537 R552 R553 R556 R593 R637 R661 R710 R751 = R_0
R154 R201 R202 R204 = R: signal model: R_0_RC0402N_0_0
R206 = R: alternate symbols: (T:RC0805N;B:RC0805M); signal model: R_0_RC0402N_0_0
R207 = R: alternate symbols: (T:RC0603N;B:RC0603M); signal model: R_0_RC0402N_0_0
R208 = R_0: signal model: R_0_RC0402N_0_0
R275 R431 R432 = R_0: alternate symbols: (T:RC0603N;B:RC0603M)
R348 R728 = R: alternate symbols: (T:RC1206N;B:RC1206M)
R522 R588 = R: signal model: R_RC0402N_20_20
R525 R587 = R: signal model: R_RC0402N_16.9_16.9
R621 R670 R761 R762 = R: alternate symbols: (T:RC0805N;B:RC0805M)
SW1 SW4 = SW-6
SW2 = SW-4_2
TP1-TP9 = TP
U1 = 1170_VLV_M_D
U3 = 8_EN25S64
U5 U8 U16 U20 U44-U46 U48 U51 U54 U60 U68 U69 = 8+1_TPS22965
U6 U26 U27 = 12_TXB0104RUTR
U7 = 8_EMC1402
U9 U19 U21 U22 U73 U84 = 5_APL3512
U10 = 56+1_PS8625QFN56G
U12 U13 = 8_AT24C02A
U14 = 15_TPD8S009
U15 = 3_APL3517
U17 = 48+1_RTL8105E/8111E
U23 = 48+1_ALC282
U24 U58 U63 = 5_SN74LVC1G08DCKR
U25 = 24+1_APW7228
U28 = 128_IT8528E/VG
U29 = 5_SN74LVC1G06DCK
U30 = 8_MX25L4005AMC-12G
U31 U41 U55 U59 = 5_APL3511
U32 U33 = 3_TPD2EUSB30DRTR
U34 U36-U40 U71 = 5_SN74AHC1G09DCK
U42 = 24+1_TPS51125RGE
U43 = 20+1_TPS51216
U47 = 14+1_tps51117RGY_2
U49 U50 U52 U53 = 10+1_APL5932C/D
U56 = 48+1_TPS59641TSL
U57 = 8+1_TPS51603/4
U61 U62 = H0056
U65 U74 = 8_TXS0102DQER
U70 = 5_APL5320
U75 = 8+1_KH25U6439F_1
U76 = 6_SY8200
U77 U83 = 28_GL850GSSOP28
U79 = 8_TLV3492
U95 = 24+1_GL834L
X1 X4 X7 X8 = OSC-4_7
X2 X5 = OSC-2
X3 X6 = OSC-4_4

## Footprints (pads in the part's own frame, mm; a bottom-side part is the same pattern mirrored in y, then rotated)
BGA71P53X56-1170N
  round 0.521 smd: A3(11.951,-11.814) A52(-12.383,-11.814) B2(12.383,-11.383) B53(-12.814,-11.383) BH1(12.814,11.383) BH53(-12.814,11.383) BJ2(12.383,11.814) BJ52(-12.383,11.814) C1(12.814,-10.951)
  round 0.406 smd: A5(11.17,-11.814) A6(10.447,-11.814) A49(-10.992,-11.814) A51(-11.773,-11.814) B52(-12.225,-11.225) BE1(12.814,9.992) BE53(-12.814,9.992) BG1(12.814,10.773) BG53(-12.814,10.773) BH2(12.225,11.225) BH52(-12.225,11.225) BJ3(11.773,11.814) BJ5(10.992,11.814) BJ49(-10.992,11.814) BJ51(-11.773,11.814) C53(-12.814,-10.773) E1(12.814,-10.17) E53(-12.814,-9.992) F1(12.814,-9.447)
  round 0.356 smd: A7(9.748,-11.814) A9(8.836,-11.814) A47(-9.621,-11.814) A48(-10.294,-11.814) B4(11.632,-11.238) B5(11.038,-11.222) B6(10.445,-11.221) B8(9.258,-11.224) B46(-9.258,-11.224) B48(-10.445,-11.221) B49(-11.038,-11.222) B50(-11.632,-11.238) BC1(12.814,8.621) BC2(12.246,8.852) BC52(-12.246,8.852) BC53(-12.814,8.621) BD1(12.814,9.294) BD2(12.221,9.445) BD52(-12.221,9.445) BD53(-12.814,9.294) BE2(12.222,10.038) BE52(-12.222,10.038) BF2(12.238,10.632) BF52(-12.238,10.632) BG3(11.644,10.644) BG51(-11.644,10.644) BH4(11.632,11.238) BH5(11.038,11.222) BH6(10.445,11.221) BH8(9.258,11.224) BH46(-9.258,11.224) BH48(-10.445,11.221) BH49(-11.038,11.222) BH50(-11.632,11.238) BJ6(10.294,11.814) BJ7(9.621,11.814) BJ47(-9.621,11.814) BJ48(-10.294,11.814) C3(11.644,-10.644) C51(-11.644,-10.644) D2(12.238,-10.632) D52(-12.238,-10.632) E2(12.222,-10.038) E52(-12.222,-10.038) F2(12.221,-9.445) F52(-12.221,-9.445) F53(-12.814,-9.294) G1(12.814,-8.679) G2(12.246,-8.852) G52(-12.246,-8.852) G53(-12.814,-8.621) J1(12.814,-7.816)
  oval 0.254x0.343 smd: A11(7.774,-11.814) A13(6.803,-11.814) A15(5.831,-11.814) A17(4.859,-11.814) A19(3.887,-11.814) A21(2.915,-11.814) A23(1.944,-11.814) A25(0.972,-11.814) A27(0,-11.814) A29(-0.972,-11.814) A31(-1.944,-11.814) A33(-2.915,-11.814) A35(-3.887,-11.814) A37(-4.859,-11.814) A39(-5.831,-11.814) A41(-6.803,-11.814) A43(-7.774,-11.814) A45(-8.746,-11.814) BJ9(8.746,11.814) BJ11(7.774,11.814) BJ13(6.803,11.814) BJ15(5.831,11.814) BJ17(4.859,11.814) BJ19(3.887,11.814) BJ21(2.915,11.814) BJ23(1.944,11.814) BJ25(0.972,11.814) BJ27(0,11.814) BJ29(-0.972,11.814) BJ31(-1.944,11.814) BJ33(-2.915,11.814) BJ35(-3.887,11.814) BJ37(-4.859,11.814) BJ39(-5.831,11.814) BJ41(-6.803,11.814) BJ43(-7.774,11.814) BJ45(-8.746,11.814)
  oval 0.343x0.254 smd: AA1(12.814,-1.944) AA53(-12.814,-1.944) AC1(12.814,-0.972) AC53(-12.814,-0.972) AE1(12.814,0) AE53(-12.814,0) AG1(12.814,0.972) AG53(-12.814,0.972) AJ1(12.814,1.944) AJ53(-12.814,1.944) AL1(12.814,2.915) AL53(-12.814,2.915) AN1(12.814,3.887) AN53(-12.814,3.887) AR1(12.814,4.859) AR53(-12.814,4.859) AU1(12.814,5.831) AU53(-12.814,5.831) AW1(12.814,6.803) AW53(-12.814,6.803) BA1(12.814,7.774) BA53(-12.814,7.774) J53(-12.814,-7.774) L1(12.814,-6.803) L53(-12.814,-6.803) N1(12.814,-5.831) N53(-12.814,-5.831) R1(12.814,-4.859) R53(-12.814,-4.859) U1(12.814,-3.887) U53(-12.814,-3.887) W1(12.814,-2.915) W53(-12.814,-2.915)
  round 0.279 smd: AA3(12.071,-1.944) AA51(-12.071,-1.944) AB2(12.429,-1.458) AB3(11.73,-1.458) AB51(-11.73,-1.458) AB52(-12.429,-1.458) AC3(12.071,-0.972) AC51(-12.071,-0.972) AD2(12.429,-0.486) AD3(11.715,-0.48) AD51(-11.715,-0.48) AD52(-12.429,-0.486) AE3(12.071,0) AE4(11.366,0) AE50(-11.366,0) AE51(-12.071,0) AF2(12.429,0.486) AF3(11.715,0.48) AF51(-11.715,0.48) AF52(-12.429,0.486) AG3(12.071,0.972) AG51(-12.071,0.972) AH2(12.429,1.458) AH3(11.73,1.458) AH51(-11.73,1.458) AH52(-12.429,1.458) AJ3(12.071,1.944) AJ51(-12.071,1.944) AK2(12.429,2.43) AK3(11.73,2.43) AK51(-11.73,2.43) AK52(-12.429,2.43) AL3(12.071,2.915) AL51(-12.071,2.915) AM2(12.429,3.401) AM3(11.73,3.401) AM51(-11.73,3.401) AM52(-12.429,3.401) AN3(12.071,3.887) AN51(-12.071,3.887) AP2(12.429,4.373) AP3(11.73,4.373) AP51(-11.73,4.373) AP52(-12.429,4.373) AR3(12.071,4.859) AR51(-12.071,4.859) AT2(12.429,5.345) AT3(11.73,5.345) AT51(-11.73,5.345) AT52(-12.429,5.345) AU3(12.071,5.831) AU51(-12.071,5.831) AV2(12.429,6.317) AV3(11.73,6.317) AV51(-11.73,6.317) AV52(-12.429,6.317) AW3(12.071,6.803) AW51(-12.071,6.803) AY2(12.429,7.289) AY3(11.73,7.289) AY51(-11.73,7.289) AY52(-12.429,7.289) B10(8.26,-11.429) B12(7.289,-11.429) B14(6.317,-11.429) B16(5.345,-11.429) B18(4.373,-11.429) B20(3.401,-11.429) B22(2.43,-11.429) B24(1.458,-11.429) B26(0.486,-11.429) B28(-0.486,-11.429) B30(-1.458,-11.429) B32(-2.43,-11.429) B34(-3.401,-11.429) B36(-4.373,-11.429) B38(-5.345,-11.429) B40(-6.317,-11.429) B42(-7.289,-11.429) B44(-8.26,-11.429) BA3(12.071,7.774) BA51(-12.071,7.774) BB3(11.929,8.351) BB51(-11.929,8.351) BF27(0,10.366) BG9(8.698,11.028) BG11(7.774,11.071) BG12(7.289,10.73) BG13(6.803,11.071) BG14(6.317,10.73) BG15(5.831,11.071) BG16(5.345,10.73) BG17(4.859,11.071) BG18(4.373,10.73) BG19(3.887,11.071) BG20(3.401,10.73) BG21(2.915,11.071) BG22(2.43,10.73) BG23(1.944,11.071) BG24(1.458,10.73) BG25(0.972,11.071) BG26(0.48,10.715) BG27(0,11.071) BG28(-0.48,10.715) BG29(-0.972,11.071) BG30(-1.458,10.73) BG31(-1.944,11.071) BG32(-2.43,10.73) BG33(-2.915,11.071) BG34(-3.401,10.73) BG35(-3.887,11.071) BG36(-4.373,10.73) BG37(-4.859,11.071) BG38(-5.345,10.73) BG39(-5.831,11.071) BG40(-6.317,10.73) BG41(-6.803,11.071) BG42(-7.289,10.73) BG43(-7.774,11.071) BG45(-8.698,11.028) BH10(8.26,11.429) BH12(7.289,11.429) BH14(6.317,11.429) BH16(5.345,11.429) BH18(4.373,11.429) BH20(3.401,11.429) BH22(2.43,11.429) BH24(1.458,11.429) BH26(0.486,11.429) BH28(-0.486,11.429) BH30(-1.458,11.429) BH32(-2.43,11.429) BH34(-3.401,11.429) BH36(-4.373,11.429) BH38(-5.345,11.429) BH40(-6.317,11.429) BH42(-7.289,11.429) BH44(-8.26,11.429) C9(8.698,-11.028) C11(7.774,-11.071) C12(7.289,-10.73) C13(6.803,-11.071) C14(6.317,-10.73) C15(5.831,-11.071) C16(5.345,-10.73) C17(4.859,-11.071) C18(4.373,-10.73) C19(3.887,-11.071) C20(3.401,-10.73) C21(2.915,-11.071) C22(2.43,-10.73) C23(1.944,-11.071) C24(1.458,-10.73) C25(0.972,-11.071) C26(0.48,-10.715) C27(0,-11.071) C28(-0.48,-10.715) C29(-0.972,-11.071) C30(-1.458,-10.73) C31(-1.944,-11.071) C32(-2.43,-10.73) C33(-2.915,-11.071) C34(-3.401,-10.73) C35(-3.887,-11.071) C36(-4.373,-10.73) C37(-4.859,-11.071) C38(-5.345,-10.73) C39(-5.831,-11.071) C40(-6.317,-10.73) C41(-6.803,-11.071) C42(-7.289,-10.73) C43(-7.774,-11.071) C45(-8.698,-11.028) D27(0,-10.366) H3(11.929,-8.351) H51(-11.929,-8.351) J3(12.071,-7.774) J51(-12.071,-7.774) K2(12.429,-7.289) K3(11.73,-7.289) K51(-11.73,-7.289) K52(-12.429,-7.289) L3(12.071,-6.803) L51(-12.071,-6.803) M2(12.429,-6.317) M3(11.73,-6.317) M51(-11.73,-6.317) M52(-12.429,-6.317) N3(12.071,-5.831) N51(-12.071,-5.831) P2(12.429,-5.345) P3(11.73,-5.345) P51(-11.73,-5.345) P52(-12.429,-5.345) R3(12.071,-4.859) R51(-12.071,-4.859) T2(12.429,-4.373) T3(11.73,-4.373) T51(-11.73,-4.373) T52(-12.429,-4.373) U3(12.071,-3.887) U51(-12.071,-3.887) V2(12.429,-3.401) V3(11.73,-3.401) V51(-11.73,-3.401) V52(-12.429,-3.401) W3(12.071,-2.915) W51(-12.071,-2.915) Y2(12.429,-2.43) Y3(11.73,-2.43) Y51(-11.73,-2.43) Y52(-12.429,-2.43)
  round 0.33 smd: AA16(5.307,-1.961) AA18(4.549,-1.961) AA19(3.791,-1.961) AA21(3.033,-1.961) AA22(2.275,-1.961) AA24(1.516,-1.961) AA25(0.758,-1.961) AA27(0,-1.961) AA29(-0.758,-1.961) AA30(-1.516,-1.961) AA32(-2.275,-1.961) AA33(-3.033,-1.961) AA35(-3.791,-1.961) AA36(-4.549,-1.961) AA38(-5.307,-1.961) AC16(5.307,-1.177) AC18(4.549,-1.177) AC19(3.791,-1.177) AC21(3.033,-1.177) AC22(2.275,-1.177) AC24(1.516,-1.177) AC25(0.758,-1.177) AC27(0,-1.177) AC29(-0.758,-1.177) AC30(-1.516,-1.177) AC32(-2.275,-1.177) AC33(-3.033,-1.177) AC35(-3.791,-1.177) AC36(-4.549,-1.177) AC38(-5.307,-1.177) AD16(5.307,-0.392) AD18(4.549,-0.392) AD19(3.791,-0.392) AD21(3.033,-0.392) AD22(2.275,-0.392) AD24(1.516,-0.392) AD25(0.758,-0.392) AD27(0,-0.392) AD29(-0.758,-0.392) AD30(-1.516,-0.392) AD32(-2.275,-0.392) AD33(-3.033,-0.392) AD35(-3.791,-0.392) AD36(-4.549,-0.392) AD38(-5.307,-0.392) AF16(5.307,0.392) AF18(4.549,0.392) AF19(3.791,0.392) AF21(3.033,0.392) AF22(2.275,0.392) AF24(1.516,0.392) AF25(0.758,0.392) AF27(0,0.392) AF29(-0.758,0.392) AF30(-1.516,0.392) AF32(-2.275,0.392) AF33(-3.033,0.392) AF35(-3.791,0.392) AF36(-4.549,0.392) AF38(-5.307,0.392) AG16(5.307,1.177) AG18(4.549,1.177) AG19(3.791,1.177) AG21(3.033,1.177) AG22(2.275,1.177) AG24(1.516,1.177) AG25(0.758,1.177) AG27(0,1.177) AG29(-0.758,1.177) AG30(-1.516,1.177) AG32(-2.275,1.177) AG33(-3.033,1.177) AG35(-3.791,1.177) AG36(-4.549,1.177) AG38(-5.307,1.177) AJ16(5.307,1.961) AJ18(4.549,1.961) AJ19(3.791,1.961) AJ21(3.033,1.961) AJ22(2.275,1.961) AJ24(1.516,1.961) AJ25(0.758,1.961) AJ27(0,1.961) AJ29(-0.758,1.961) AJ30(-1.516,1.961) AJ32(-2.275,1.961) AJ33(-3.033,1.961) AJ35(-3.791,1.961) AJ36(-4.549,1.961) AJ38(-5.307,1.961) AK16(5.307,2.745) AK18(4.549,2.745) AK19(3.791,2.745) AK21(3.033,2.745) AK22(2.275,2.745) AK24(1.516,2.745) AK25(0.758,2.745) AK27(0,2.745) AK29(-0.758,2.745) AK30(-1.516,2.745) AK32(-2.275,2.745) AK33(-3.033,2.745) AK35(-3.791,2.745) AK36(-4.549,2.745) AK38(-5.307,2.745) AM16(5.307,3.53) AM18(4.549,3.53) AM19(3.791,3.53) AM21(3.033,3.53) AM22(2.275,3.53) AM24(1.516,3.53) AM25(0.758,3.53) AM27(0,3.53) AM29(-0.758,3.53) AM30(-1.516,3.53) AM32(-2.275,3.53) AM33(-3.033,3.53) AM35(-3.791,3.53) AM36(-4.549,3.53) AM38(-5.307,3.53) AN16(5.307,4.314) AN18(4.549,4.314) AN19(3.791,4.314) AN21(3.033,4.314) AN22(2.275,4.314) AN24(1.516,4.314) AN25(0.758,4.314) AN27(0,4.314) AN29(-0.758,4.314) AN30(-1.516,4.314) AN32(-2.275,4.314) AN33(-3.033,4.314) AN35(-3.791,4.314) AN36(-4.549,4.314) AN38(-5.307,4.314) U16(5.307,-4.314) U18(4.549,-4.314) U19(3.791,-4.314) U21(3.033,-4.314) U22(2.275,-4.314) U24(1.516,-4.314) U25(0.758,-4.314) U27(0,-4.314) U29(-0.758,-4.314) U30(-1.516,-4.314) U32(-2.275,-4.314) U33(-3.033,-4.314) U35(-3.791,-4.314) U36(-4.549,-4.314) U38(-5.307,-4.314) V16(5.307,-3.53) V18(4.549,-3.53) V19(3.791,-3.53) V21(3.033,-3.53) V22(2.275,-3.53) V24(1.516,-3.53) V25(0.758,-3.53) V27(0,-3.53) V29(-0.758,-3.53) V30(-1.516,-3.53) V32(-2.275,-3.53) V33(-3.033,-3.53) V35(-3.791,-3.53) V36(-4.549,-3.53) V38(-5.307,-3.53) Y16(5.307,-2.745) Y18(4.549,-2.745) Y19(3.791,-2.745) Y21(3.033,-2.745) Y22(2.275,-2.745) Y24(1.516,-2.745) Y25(0.758,-2.745) Y27(0,-2.745) Y29(-0.758,-2.745) Y30(-1.516,-2.745) Y32(-2.275,-2.745) Y33(-3.033,-2.745) Y35(-3.791,-2.745) Y36(-4.549,-2.745) Y38(-5.307,-2.745)
  round 0.305 smd: AB4(11.137,-1.448) AB6(10.463,-1.448) AB7(9.752,-1.448) AB9(9.041,-1.448) AB10(8.33,-1.448) AB12(7.618,-1.448) AB13(6.907,-1.448) AB14(6.196,-1.448) AB40(-6.196,-1.448) AB41(-6.907,-1.448) AB42(-7.618,-1.448) AB44(-8.33,-1.448) AB45(-9.041,-1.448) AB47(-9.752,-1.448) AB48(-10.463,-1.448) AB50(-11.137,-1.448) AD4(10.995,-0.463) AD6(10.404,-0.525) AD7(9.752,-0.475) AD9(9.041,-0.475) AD10(8.33,-0.475) AD12(7.618,-0.475) AD13(6.907,-0.475) AD14(6.196,-0.475) AD40(-6.196,-0.475) AD41(-6.907,-0.475) AD42(-7.618,-0.475) AD44(-8.33,-0.475) AD45(-9.041,-0.475) AD47(-9.752,-0.475) AD48(-10.404,-0.525) AD50(-10.995,-0.463) AE6(10.108,0) AE8(9.396,0) AE9(8.685,0) AE11(7.974,0) AE12(7.263,0) AE14(6.552,0) AE40(-6.552,0) AE42(-7.263,0) AE43(-7.974,0) AE45(-8.685,0) AE46(-9.396,0) AE48(-10.108,0) AF4(10.995,0.463) AF6(10.404,0.525) AF7(9.752,0.475) AF9(9.041,0.475) AF10(8.33,0.475) AF12(7.618,0.475) AF13(6.907,0.475) AF14(6.196,0.475) AF40(-6.196,0.475) AF41(-6.907,0.475) AF42(-7.618,0.475) AF44(-8.33,0.475) AF45(-9.041,0.475) AF47(-9.752,0.475) AF48(-10.404,0.525) AF50(-10.995,0.463) AH4(11.137,1.448) AH6(10.463,1.448) AH7(9.752,1.448) AH9(9.041,1.448) AH10(8.33,1.448) AH12(7.618,1.448) AH13(6.907,1.448) AH14(6.196,1.448) AH40(-6.196,1.448) AH41(-6.907,1.448) AH42(-7.618,1.448) AH44(-8.33,1.448) AH45(-9.041,1.448) AH47(-9.752,1.448) AH48(-10.463,1.448) AH50(-11.137,1.448) AK4(11.137,2.439) AK6(10.463,2.439) AK7(9.752,2.439) AK9(9.041,2.439) AK10(8.33,2.439) AK12(7.618,2.439) AK13(6.907,2.439) AK14(6.196,2.439) AK40(-6.196,2.439) AK41(-6.907,2.439) AK42(-7.618,2.439) AK44(-8.33,2.439) AK45(-9.041,2.439) AK47(-9.752,2.439) AK48(-10.463,2.439) AK50(-11.137,2.439) AM4(11.137,3.386) AM6(10.463,3.412) AM7(9.752,3.412) AM9(9.041,3.412) AM10(8.33,3.412) AM12(7.618,3.412) AM13(6.907,3.412) AM14(6.196,3.412) AM40(-6.196,3.412) AM41(-6.907,3.412) AM42(-7.618,3.412) AM44(-8.33,3.412) AM45(-9.041,3.412) AM47(-9.752,3.412) AM48(-10.463,3.412) AM50(-11.137,3.386) AN5(10.819,3.887) AN6(10.108,3.887) AN8(9.396,3.887) AN9(8.685,3.887) AN11(7.974,3.887) AN12(7.263,3.887) AN14(6.552,3.887) AN40(-6.552,3.887) AN42(-7.263,3.887) AN43(-7.974,3.887) AN45(-8.685,3.887) AN46(-9.396,3.887) AN48(-10.108,3.887) AN49(-10.819,3.887) AP4(11.137,4.388) AP6(10.463,4.362) AP7(9.752,4.362) AP9(9.041,4.362) AP10(8.33,4.362) AP12(7.618,4.362) AP13(6.907,4.362) AP14(6.196,4.362) AP40(-6.196,4.362) AP41(-6.907,4.362) AP42(-7.618,4.362) AP44(-8.33,4.362) AP45(-9.041,4.362) AP47(-9.752,4.362) AP48(-10.463,4.362) AP50(-11.137,4.388) AT4(11.137,5.336) AT6(10.463,5.336) AT7(9.752,5.336) AT9(9.041,5.336) AT10(8.33,5.336) AT12(7.618,5.336) AT13(6.907,5.336) AT14(6.305,5.336) AT16(5.336,5.196) AT18(4.362,5.196) AT19(3.887,5.552) AT20(3.412,5.196) AT22(2.439,5.196) AT24(1.448,5.196) AT26(0.475,5.196) AT27(0,5.552) AT28(-0.475,5.196) AT30(-1.448,5.196) AT32(-2.439,5.196) AT34(-3.412,5.196) AT35(-3.887,5.552) AT36(-4.362,5.196) AT38(-5.336,5.196) AT40(-6.305,5.336) AT41(-6.907,5.336) AT42(-7.618,5.336) AT44(-8.33,5.336) AT45(-9.041,5.336) AT47(-9.752,5.336) AT48(-10.463,5.336) AT50(-11.137,5.336) AU16(5.336,5.907) AU18(4.362,5.907) AU20(3.412,5.907) AU22(2.439,5.907) AU24(1.448,5.907) AU26(0.475,5.907) AU28(-0.475,5.907) AU30(-1.448,5.907) AU32(-2.439,5.907) AU34(-3.412,5.907) AU36(-4.362,5.907) AU38(-5.336,5.907) AV4(11.137,6.326) AV6(10.463,6.326) AV7(9.752,6.326) AV9(9.041,6.326) AV10(8.33,6.326) AV12(7.618,6.326) AV13(6.907,6.326) AV14(6.326,6.446) AV16(5.336,6.618) AV18(4.362,6.618) AV19(3.887,6.263) AV20(3.412,6.618) AV22(2.439,6.618) AV24(1.448,6.618) AV26(0.475,6.618) AV27(0,6.263) AV28(-0.475,6.618) AV30(-1.448,6.618) AV32(-2.439,6.618) AV34(-3.412,6.618) AV35(-3.887,6.263) AV36(-4.362,6.618) AV38(-5.336,6.618) AV40(-6.326,6.446) AV41(-6.907,6.326) AV42(-7.618,6.326) AV44(-8.33,6.326) AV45(-9.041,6.326) AV47(-9.752,6.326) AV48(-10.463,6.326) AV50(-11.137,6.326) AW13(6.751,6.915) AW19(3.887,6.974) AW27(0,6.974) AW35(-3.887,6.974) AW41(-6.751,6.915) AY4(11.137,7.317) AY6(10.463,7.317) AY7(9.752,7.317) AY9(9.041,7.317) AY10(8.33,7.317) AY12(7.317,7.34) AY14(6.326,7.33) AY16(5.336,7.33) AY18(4.362,7.33) AY20(3.412,7.33) AY22(2.439,7.33) AY24(1.448,7.33) AY26(0.475,7.33) AY28(-0.475,7.33) AY30(-1.448,7.33) AY32(-2.439,7.33) AY34(-3.412,7.33) AY36(-4.362,7.33) AY38(-5.336,7.33) AY40(-6.326,7.33) AY42(-7.317,7.34) AY44(-8.33,7.317) AY45(-9.041,7.317) AY47(-9.752,7.317) AY48(-10.463,7.317) AY50(-11.137,7.317) B7(9.852,-11.23) B47(-9.852,-11.23) BA12(7.317,8.041) BA14(6.326,8.041) BA16(5.336,8.041) BA18(4.362,8.041) BA19(3.887,7.685) BA20(3.412,8.041) BA22(2.439,8.041) BA24(1.448,8.041) BA26(0.475,8.041) BA27(0,7.685) BA28(-0.475,8.041) BA30(-1.448,8.041) BA32(-2.439,8.041) BA34(-3.412,8.041) BA35(-3.887,7.685) BA36(-4.362,8.041) BA38(-5.336,8.041) BA40(-6.326,8.041) BA42(-7.317,8.041) BB4(11.258,8.307) BB5(10.547,8.307) BB7(9.835,8.307) BB8(9.124,8.307) BB10(8.307,8.17) BB19(3.887,8.396) BB27(0,8.396) BB35(-3.887,8.396) BB44(-8.307,8.17) BB46(-9.124,8.307) BB47(-9.835,8.307) BB49(-10.547,8.307) BB50(-11.258,8.307) BC10(8.307,8.764) BC12(7.317,8.752) BC14(6.326,8.752) BC16(5.336,8.752) BC18(4.362,8.752) BC20(3.412,8.752) BC22(2.439,8.752) BC24(1.448,8.752) BC26(0.475,8.752) BC28(-0.475,8.752) BC30(-1.448,8.752) BC32(-2.439,8.752) BC34(-3.412,8.752) BC36(-4.362,8.752) BC38(-5.336,8.752) BC40(-6.326,8.752) BC42(-7.317,8.752) BC44(-8.307,8.764) BD5(10.565,9.302) BD7(9.712,9.302) BD10(8.307,9.457) BD12(7.317,9.463) BD14(6.326,9.463) BD16(5.336,9.463) BD18(4.362,9.463) BD19(3.887,9.108) BD20(3.412,9.463) BD22(2.439,9.463) BD24(1.448,9.463) BD26(0.525,9.404) BD27(0,9.108) BD28(-0.525,9.404) BD30(-1.448,9.463) BD32(-2.439,9.463) BD34(-3.412,9.463) BD35(-3.887,9.108) BD36(-4.362,9.463) BD38(-5.336,9.463) BD40(-6.326,9.463) BD42(-7.317,9.463) BD44(-8.307,9.457) BD47(-9.712,9.302) BD49(-10.565,9.302) BE3(11.643,9.58) BE8(9.32,9.747) BE19(3.887,9.819) BE35(-3.887,9.819) BE46(-9.32,9.747) BE51(-11.643,9.58) BF4(11.163,10.163) BF6(10.113,10.238) BF10(8.307,10.168) BF12(7.317,10.137) BF14(6.326,10.137) BF16(5.336,10.137) BF18(4.388,10.137) BF20(3.386,10.137) BF22(2.439,10.137) BF24(1.448,10.137) BF26(0.463,9.995) BF28(-0.463,9.995) BF30(-1.448,10.137) BF32(-2.439,10.137) BF34(-3.386,10.137) BF36(-4.388,10.137) BF38(-5.336,10.137) BF40(-6.326,10.137) BF42(-7.317,10.137) BF44(-8.307,10.168) BF48(-10.113,10.238) BF50(-11.163,10.163) BG5(10.58,10.643) BG7(9.553,10.709) BG47(-9.553,10.709) BG49(-10.58,10.643) BH7(9.852,11.23) BH47(-9.852,11.23) C5(10.58,-10.643) C7(9.553,-10.709) C47(-9.553,-10.709) C49(-10.58,-10.643) D4(11.163,-10.163) D6(10.113,-10.238) D10(8.307,-10.168) D12(7.317,-10.137) D14(6.326,-10.137) D16(5.336,-10.137) D18(4.388,-10.137) D20(3.386,-10.137) D22(2.439,-10.137) D24(1.448,-10.137) D26(0.463,-9.995) D28(-0.463,-9.995) D30(-1.448,-10.137) D32(-2.439,-10.137) D34(-3.386,-10.137) D36(-4.388,-10.137) D38(-5.336,-10.137) D40(-6.326,-10.137) D42(-7.317,-10.137) D44(-8.307,-10.168) D48(-10.113,-10.238) D50(-11.163,-10.163) E3(11.643,-9.58) E8(9.32,-9.747) E19(3.887,-9.819) E35(-3.887,-9.819) E46(-9.32,-9.747) E51(-11.643,-9.58) F5(10.565,-9.302) F7(9.712,-9.302) F10(8.307,-9.457) F12(7.317,-9.463) F14(6.326,-9.463) F16(5.336,-9.463) F18(4.362,-9.463) F19(3.887,-9.108) F20(3.412,-9.463) F22(2.439,-9.463) F24(1.448,-9.463) F26(0.525,-9.404) F27(0,-9.108) F28(-0.525,-9.404) F30(-1.448,-9.463) F32(-2.439,-9.463) F34(-3.412,-9.463) F35(-3.887,-9.108) F36(-4.362,-9.463) F38(-5.336,-9.463) F40(-6.326,-9.463) F42(-7.317,-9.463) F44(-8.307,-9.457) F47(-9.712,-9.302) F49(-10.565,-9.302) G10(8.307,-8.764) G12(7.317,-8.752) G14(6.326,-8.752) G16(5.336,-8.752) G18(4.362,-8.752) G20(3.412,-8.752) G22(2.439,-8.752) G24(1.448,-8.752) G26(0.475,-8.752) G28(-0.475,-8.752) G30(-1.448,-8.752) G32(-2.439,-8.752) G34(-3.412,-8.752) G36(-4.362,-8.752) G38(-5.336,-8.752) G40(-6.326,-8.752) G42(-7.317,-8.752) G44(-8.307,-8.764) H4(11.258,-8.307) H5(10.547,-8.307) H7(9.835,-8.307) H8(9.124,-8.307) H10(8.307,-8.17) H19(3.887,-8.396) H27(0,-8.396) H35(-3.887,-8.396) H44(-8.307,-8.17) H46(-9.124,-8.307) H47(-9.835,-8.307) H49(-10.547,-8.307) H50(-11.258,-8.307) J12(7.317,-8.041) J14(6.326,-8.041) J16(5.336,-8.041) J18(4.362,-8.041) J19(3.887,-7.685) J20(3.412,-8.041) J22(2.439,-8.041) J24(1.448,-8.041) J26(0.475,-8.041) J27(0,-7.685) J28(-0.475,-8.041) J30(-1.448,-8.041) J32(-2.439,-8.041) J34(-3.412,-8.041) J35(-3.887,-7.685) J36(-4.362,-8.041) J38(-5.336,-8.041) J40(-6.326,-8.041) J42(-7.317,-8.041) K4(11.137,-7.317) K6(10.463,-7.317) K7(9.752,-7.317) K9(9.041,-7.317) K10(8.33,-7.317) K12(7.317,-7.34) K14(6.326,-7.33) K16(5.336,-7.33) K18(4.362,-7.33) K20(3.412,-7.33) K22(2.439,-7.33) K24(1.448,-7.33) K26(0.475,-7.33) K28(-0.475,-7.33) K30(-1.448,-7.33) K32(-2.439,-7.33) K34(-3.412,-7.33) K36(-4.362,-7.33) K38(-5.336,-7.33) K40(-6.326,-7.33) K42(-7.317,-7.34) K44(-8.33,-7.317) K45(-9.041,-7.317) K47(-9.752,-7.317) K48(-10.463,-7.317) K50(-11.137,-7.317) L13(6.751,-6.915) L19(3.887,-6.974) L27(0,-6.974) L35(-3.887,-6.974) L41(-6.751,-6.915) M4(11.137,-6.326) M6(10.463,-6.326) M7(9.752,-6.326) M9(9.041,-6.326) M10(8.33,-6.326) M12(7.618,-6.326) M13(6.907,-6.326) M14(6.326,-6.446) M16(5.336,-6.618) M18(4.362,-6.618) M19(3.887,-6.263) M20(3.412,-6.618) M22(2.439,-6.618) M24(1.448,-6.618) M26(0.475,-6.618) M27(0,-6.263) M28(-0.475,-6.618) M30(-1.448,-6.618) M32(-2.439,-6.618) M34(-3.412,-6.618) M35(-3.887,-6.263) M36(-4.362,-6.618) M38(-5.336,-6.618) M40(-6.326,-6.446) M41(-6.907,-6.326) M42(-7.618,-6.326) M44(-8.33,-6.326) M45(-9.041,-6.326) M47(-9.752,-6.326) M48(-10.463,-6.326) M50(-11.137,-6.326) N16(5.336,-5.907) N18(4.362,-5.907) N20(3.412,-5.907) N22(2.439,-5.907) N24(1.448,-5.907) N26(0.475,-5.907) N28(-0.475,-5.907) N30(-1.448,-5.907) N32(-2.439,-5.907) N34(-3.412,-5.907) N36(-4.362,-5.907) N38(-5.336,-5.907) P4(11.137,-5.336) P6(10.463,-5.336) P7(9.752,-5.336) P9(9.041,-5.336) P10(8.33,-5.336) P12(7.618,-5.336) P13(6.907,-5.336) P14(6.305,-5.336) P16(5.336,-5.196) P18(4.362,-5.196) P19(3.887,-5.552) P20(3.412,-5.196) P22(2.439,-5.196) P24(1.448,-5.196) P26(0.475,-5.196) P27(0,-5.552) P28(-0.475,-5.196) P30(-1.448,-5.196) P32(-2.439,-5.196) P34(-3.412,-5.196) P35(-3.887,-5.552) P36(-4.362,-5.196) P38(-5.336,-5.196) P40(-6.305,-5.336) P41(-6.907,-5.336) P42(-7.618,-5.336) P44(-8.33,-5.336) P45(-9.041,-5.336) P47(-9.752,-5.336) P48(-10.463,-5.336) P50(-11.137,-5.336) T4(11.137,-4.388) T6(10.463,-4.362) T7(9.752,-4.362) T9(9.041,-4.362) T10(8.33,-4.362) T12(7.618,-4.362) T13(6.907,-4.362) T14(6.196,-4.362) T40(-6.196,-4.362) T41(-6.907,-4.362) T42(-7.618,-4.362) T44(-8.33,-4.362) T45(-9.041,-4.362) T47(-9.752,-4.362) T48(-10.463,-4.362) T50(-11.137,-4.388) U5(10.819,-3.887) U6(10.108,-3.887) U8(9.396,-3.887) U9(8.685,-3.887) U11(7.974,-3.887) U12(7.263,-3.887) U14(6.552,-3.887) U40(-6.552,-3.887) U42(-7.263,-3.887) U43(-7.974,-3.887) U45(-8.685,-3.887) U46(-9.396,-3.887) U48(-10.108,-3.887) U49(-10.819,-3.887) V4(11.137,-3.386) V6(10.463,-3.412) V7(9.752,-3.412) V9(9.041,-3.412) V10(8.33,-3.412) V12(7.618,-3.412) V13(6.907,-3.412) V14(6.196,-3.412) V40(-6.196,-3.412) V41(-6.907,-3.412) V42(-7.618,-3.412) V44(-8.33,-3.412) V45(-9.041,-3.412) V47(-9.752,-3.412) V48(-10.463,-3.412) V50(-11.137,-3.386) Y4(11.137,-2.439) Y6(10.463,-2.439) Y7(9.752,-2.439) Y9(9.041,-2.439) Y10(8.33,-2.439) Y12(7.618,-2.439) Y13(6.907,-2.439) Y14(6.196,-2.439) Y40(-6.196,-2.439) Y41(-6.907,-2.439) Y42(-7.618,-2.439) Y44(-8.33,-2.439) Y45(-9.041,-2.439) Y47(-9.752,-2.439) Y48(-10.463,-2.439) Y50(-11.137,-2.439)
